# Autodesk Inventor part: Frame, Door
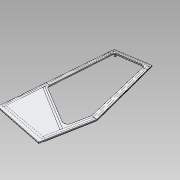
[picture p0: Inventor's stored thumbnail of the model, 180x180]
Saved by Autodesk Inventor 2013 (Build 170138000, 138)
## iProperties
Created: 2012-10
Part Number: Frame, Door
Material: Aluminum 6061
Document SubType Name: Modeling
Designer: VMuser
Density: 2.71 g/cm^3
Mass: 5407.9 g
Surface Area: 18192.7 cm^2
Volume: 1995.54 cm^3
Author: VMuser
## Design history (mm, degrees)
derived "Frame, Door.iam"
body "Solid1"
node "PK46.51.11.011.ipt:1"
node "PK46.51.11.014.ipt:1"
node "PK46.51.11.013.ipt:1"
node "PK46.51.11.021.ipt:1"
node "PK46.51.11.023.ipt:1"
node "PK46.51.11.025.ipt:1"
node "PK46.51.11.024.ipt:1"
node "PK46.51.11.031.ipt:1"
node "PK46.51.11.033.ipt:1"
node "PK46.51.11.035.ipt:1"
node "PK46.51.11.034.ipt:1"
node "PK46.51.11.022.ipt:1"
node "PK46.51.11.032.ipt:1"
node "Support gas.ipt:1"
node "PK46.51.11.026.ipt:1"
node "PK46.51.11.016-01.ipt:1"
node "PK46.51.11.016.ipt:1"
node "PK46.51.11.012(new).ipt:1"
node "Frame, Door.iam_Bodies"
